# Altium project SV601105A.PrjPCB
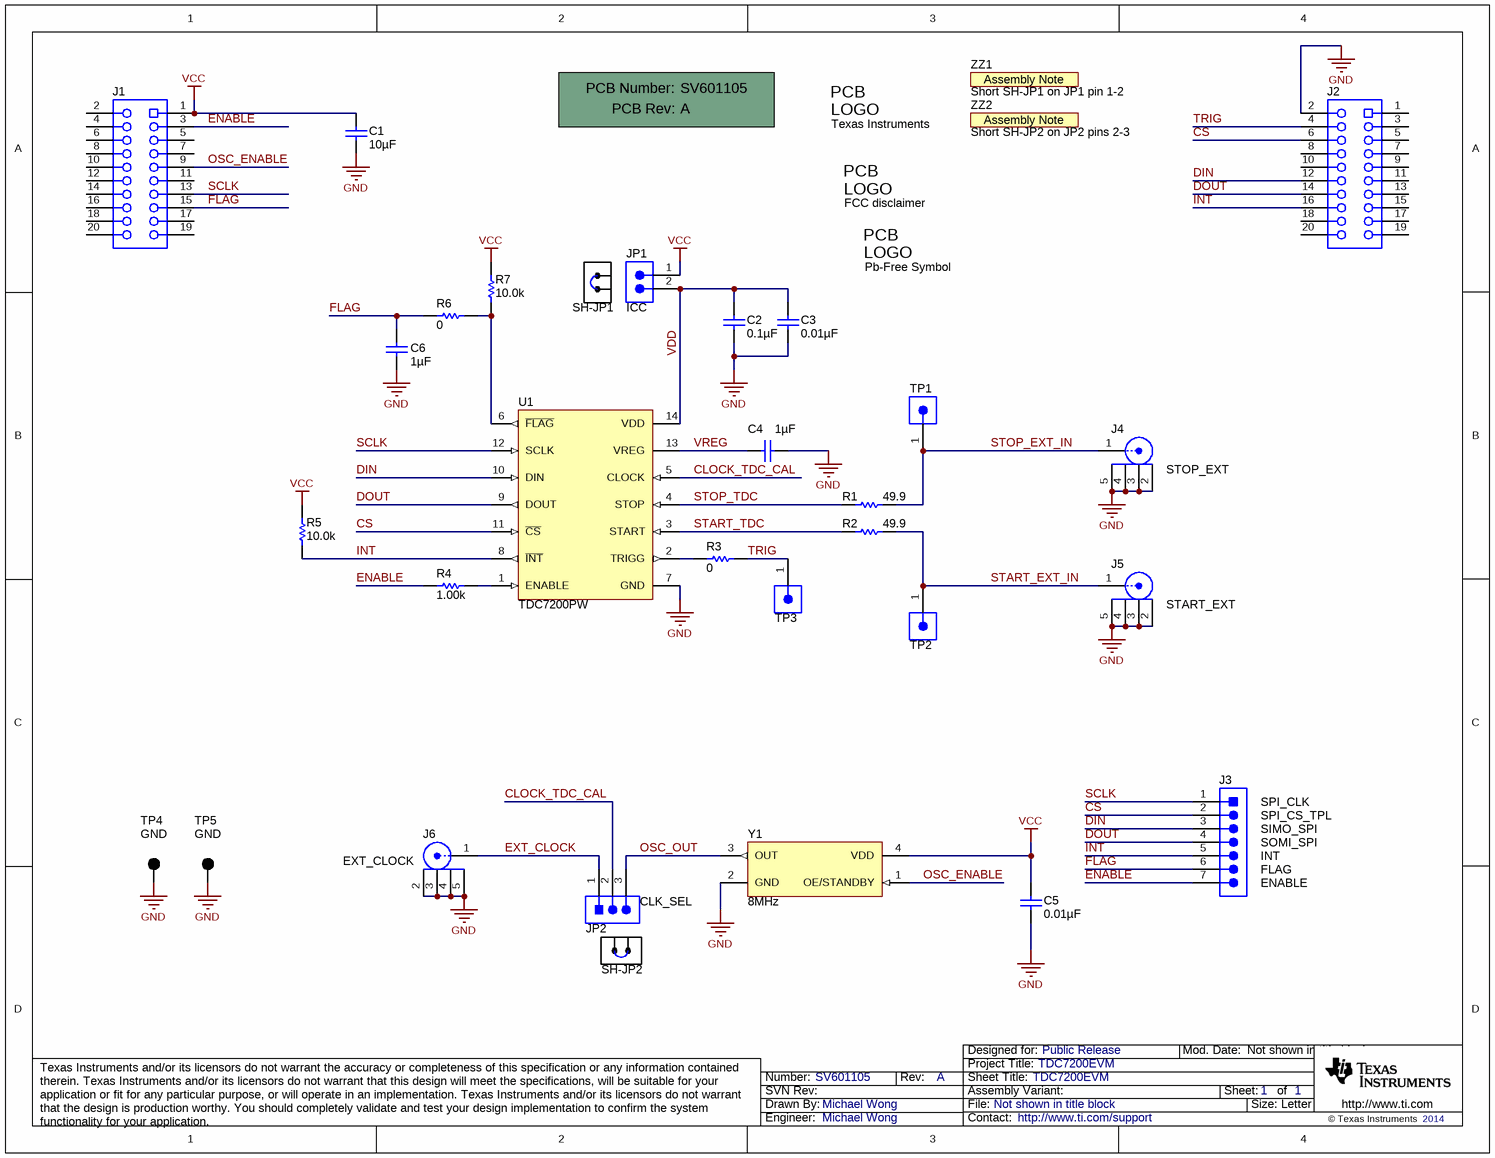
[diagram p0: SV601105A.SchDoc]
CopyrightYear: 2014; PCB_Layout: Michael Wong; PCB_Rev: A; PRJ_Customer: Public Release; PRJ_Engineer: Michael Wong; PRJ_Number: SV601105; PRJ_Title: TDC7200EVM; SCH_Rev: A; TechSupport: http://www.ti.com/support
1 sheet, 36 parts. Net scope: global (net labels, ports and power ports of the same name join across sheets).
Board file: SV601105A.PcbDoc

## Sheet SV601105A.SchDoc: TDC7200EVM
size Letter; Date: Not shown in title block; ApprovedBy: Not shown in title block; CheckedBy: Not shown in title block; Author: Not shown in title block; CompanyName: Not shown in title block; DrawnBy: Michael Wong; Engineer: Michael Wong; Organization: Not shown in title block; Address1: Not shown in title block; Address2: Not shown in title block; Address3: Not shown in title block; Address4: Not shown in title block; DocumentNumber: 1; Revision: Use project parameter SCH_Rev; SheetNumber: 1; SheetTotal: 1; PageSetup: Record=PageOptions|CenterHorizontal=True|CenterVertical=True|PrintScale=1.00|XCorrection=1.00|YCorrection=1.00|PrintKind=0|BorderSize=5000000|LeftOffset=0|BottomOffset=0|Orientation=2|PaperLength=1000|PaperWidth=1000|Scale=100|PaperSource=15|PrintQuality=600|MediaType=1|DitherType=10|PaperKind=Letter|PrintScaleMode=1

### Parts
!PCB  Printed Circuit Board  (value not drawn)  (mechanical)
C1  ValueDisplayed: 10µF  [0603]  (hidden comment: C0603C106M9PACTU)
C2  ValueDisplayed: 0.1µF  [0603]  (hidden comment: 0603YC104JAT2A)
C3  ValueDisplayed: 0.01µF  [0603]  (hidden comment: 06031C103JAT2A)
C4  ValueDisplayed: 1µF  [0603]  (hidden comment: EMK107B7105KA-T)
C5  ValueDisplayed: 0.01µF  [0603]  (hidden comment: 06031C103JAT2A)
C6  ValueDisplayed: 1µF  [0603]  (hidden comment: EMK107B7105KA-T)
J1  PPPC102LFBN-RC  [Sullins_PPPC102LFBN-RC]  (value not drawn)
J2  PPPC102LFBN-RC  [Sullins_PPPC102LFBN-RC]  (value not drawn)
J3  TSW-107-07-G-S  [TSW-107-07-G-S]  (value not drawn)
J4  STOP_EXT  [JOHNSON_142-0701-801]
J5  START_EXT  [JOHNSON_142-0701-801]
J6  EXT_CLOCK  [JOHNSON_142-0701-801]
JP1  ICC  [TSW-102-07-G-S]
JP2  CLK_SEL  [TSW-103-07-G-S]
Logo1  Texas Instruments  [TI_Stacked_Overlay_Small]  (no BOM)
Logo2  FCC disclaimer  [FCC_disclaimer_stacked]  (no BOM)
Logo3  Pb-Free Symbol  [Pb-Free_Overlay_Medium]  (no BOM)
R1  value 49.9  [0603]  (hidden comment: CRCW060349R9FKEA)
R2  value 49.9  [0603]  (hidden comment: CRCW060349R9FKEA)
R3  value 0  [0603]  (hidden comment: CRCW06030000Z0EA)
R4  value 1.00k  [0603]  (hidden comment: CRCW06031K00FKEA)
R5  value 10.0k  [0603]  (hidden comment: CRCW060310K0FKEA)
R6  value 0  [0603]  (hidden comment: CRCW06030000Z0EA)
R7  value 10.0k  [0603]  (hidden comment: CRCW060310K0FKEA)
SH-JP1  969102-0000-DA  [SNT-100-BK-G]  (value not drawn)  (mechanical)
SH-JP2  969102-0000-DA  [SNT-100-BK-G]  (value not drawn)  (mechanical)
TP1  TSW-101-07-G-S  [TSW-101-07-G-S]  (value not drawn)
TP2  TSW-101-07-G-S  [TSW-101-07-G-S]  (value not drawn)
TP3  TSW-101-07-G-S  [TSW-101-07-G-S]  (value not drawn)
TP4  GND  [Keystone5011]
TP5  GND  [Keystone5011]
U1  TDC7200PW  [PW0014A_N]
Y1  Frequency: 8MHz  [Abracon_ASFLMB]  (hidden comment: ASFLMB-8.000MHZ-LY-T)
ZZ1  Short SH-JP1 on JP1 pin 1-2  [AssemblyNote]  (no BOM)
ZZ2  Short SH-JP2 on JP2 pins 2-3  [AssemblyNote]  (no BOM)

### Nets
GND: C1.2 C2.2 C3.2 C4.1 C5.2 C6.2 J2.2 J4.2 J4.3 J4.4 J4.5 J5.2 J5.3 J5.4 J5.5 J6.2 J6.3 J6.4 J6.5 TP4.1 TP5.1 U1.7(GND) Y1.2(GND)
VCC: C1.1 C5.1 J1.1 JP1.1 R5.2 R7.2 Y1.4(VDD)
CLOCK_TDC_CAL: JP2.2 U1.5(CLOCK)
CS: J2.6 J3.2 U1.11(~{CS})
DIN: J2.12 J3.3 U1.10(DIN)
DOUT: J2.14 J3.4 U1.9(DOUT)
ENABLE: J1.3 J3.7 R4.1
EXT_CLOCK: J6.1 JP2.1
FLAG: C6.1 J1.15 J3.6 R6.1
INT: J2.16 J3.5 R5.1 U1.8(~{INT})
OSC_ENABLE: J1.9 Y1.1(OE/STANDBY)
OSC_OUT: JP2.3 Y1.3(OUT)
SCLK: J1.13 J3.1 U1.12(SCLK)
START_EXT_IN: J5.1 R2.2 TP2.1
START_TDC: R2.1 U1.3(START)
STOP_EXT_IN: J4.1 R1.2 TP1.1
STOP_TDC: R1.1 U1.4(STOP)
TRIG: J2.4 R3.2 TP3.1
VDD: C2.1 C3.1 JP1.2 U1.14(VDD)
VREG: C4.2 U1.13(VREG)
NetR3_1: R3.1 U1.2(TRIGG)
NetR4_2: R4.2 U1.1(ENABLE)
NetR6_2: R6.2 R7.1 U1.6(~{FLAG})

Not connected (* = marked no-connect by the designer): J1 2 4 5 6 7 8 10 11 12 14 16 17 18 19 20; J2 1 3 5 7 8 9 10 11 13 15 17 18 19 20

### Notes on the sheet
- (near J3) SPI_CLK
- (near J3) SPI_CS_TPL
- (near J3) SIMO_SPI
- (near J3) SOMI_SPI
- (near J3) ENABLE
- (near J3) INT
- (near J3) FLAG

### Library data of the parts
!PCB = PCB: Manufacturer: Any; PartNumber: SV601105; SymbolCreator: a0412235
C1 = C0603C106M9PACTU: CAP, CERM, 10uF, 6.3V, +/-20%, X5R, 0603; Manufacturer: Kemet; Polarized: N; CompType: Capacitor; U/M: EA; Cap_F: 0.00001; Tolerance_%: 20; ESR_Ohm: 0.004; Value1: 0.004 ohm; VDC_V: 6.3; IRMS_A: 8.9; TaMin_C: -55; TaMax_C: 85
C2 = 0603YC104JAT2A: CAP, CERM, 0.1uF, 16V, +/-5%, X7R, 0603; Manufacturer: AVX; Polarized: N; CompType: Capacitor; U/M: EA; Cap_F: 0.0000001; Tolerance_%: 5; ESR_Ohm: 0.039; Value1: 0.039 ohm; VDC_V: 16; TaMin_C: -55; TaMax_C: 125
C3 C5 = 06031C103JAT2A: CAP, CERM, 0.01uF, 100V, +/-5%, X7R, 0603; Manufacturer: AVX; Polarized: N; CompType: Capacitor; U/M: EA; Cap_F: 0.00000001; Tolerance_%: 5; ESR_Ohm: 0.098; Value1: 0.098 ohm; VDC_V: 100; TaMin_C: -55; TaMax_C: 125
C4 C6 = EMK107B7105KA-T: CAP, CERM, 1uF, 16V, +/-10%, X7R, 0603; Manufacturer: Taiyo Yuden; Polarized: N; CompType: Capacitor; U/M: EA; Cap_F: 0.000001; Tolerance_%: 10; Value1: Unknown; VDC_V: 16; TaMin_C: -55; TaMax_C: 85
J1 J2 = PPPC102LFBN-RC: Receptacle, 10x2, 100mil, TH; Manufacturer: Sullins Connector Solutions; SymbolCreator: a0412235; U/M: EA
J3 = TSW-107-07-G-S: Header, TH, 100mil, 7x1, Gold plated, 230 mil above insulator; Manufacturer: Samtec; SymbolCreator: a0411947; U/M: EA
J4-J6 = 142-0701-801: Connector, End launch SMA, 50 ohm, SMT; Manufacturer: Johnson; SymbolCreator: X0208326; U/M: EA
JP1 = TSW-102-07-G-S: Header, TH, 100mil, 2x1, Gold plated, 230 mil above insulator; Manufacturer: Samtec; SymbolCreator: a0412235; U/M: EA
JP2 = TSW-103-07-G-S: Header, TH, 100mil, 3x1, Gold plated, 230 mil above insulator; Manufacturer: Samtec; SymbolCreator: a0799628; U/M: EA
Logo1 = TI_Logo: Texas Instrument Corporate Signature; SymbolCreator: codlsc
Logo2 = FCC_disclaimer: SymbolCreator: codlsc
Logo3 = Pb-Free: SymbolCreator: a0412235
R1 R2 = CRCW060349R9FKEA: RES, 49.9 ohm, 1%, 0.1W, 0603; Manufacturer: Vishay-Dale; CompType: Resistor; Value_Code: 49R9; Tolerance_%: 1; Power_W: 0.1; VDC_V: 75; TempCo: 100 ppm/C; EIA_Code: E96; U/M: EA
R3 R6 = CRCW06030000Z0EA: RES, 0 ohm, 5%, 0.1W, 0603; Manufacturer: Vishay-Dale; CompType: Resistor; Value_Code: 0000; Tolerance_%: 5; Power_W: 0.1; VDC_V: 75; TempCo: 200 ppm/C; EIA_Code: E24; U/M: EA
R4 = CRCW06031K00FKEA: RES, 1.00k ohm, 1%, 0.1W, 0603; Manufacturer: Vishay-Dale; CompType: Resistor; Res_ohm: 1000; Value_Code: 1k00; Tolerance_%: 1; Power_W: 0.1; VDC_V: 75; TempCo: 100 ppm/C; EIA_Code: E96; U/M: EA
R5 R7 = CRCW060310K0FKEA: RES, 10.0k ohm, 1%, 0.1W, 0603; Manufacturer: Vishay-Dale; CompType: Resistor; Res_ohm: 10000; Value_Code: 10k0; Tolerance_%: 1; Power_W: 0.1; VDC_V: 75; TempCo: 100 ppm/C; EIA_Code: E96; U/M: EA
SH-JP1 SH-JP2 = 969102-0000-DA: Shunt, 100mil, Gold plated, Black; Manufacturer: 3M; Alternate Manufacturer: Samtec; Value: 1x2; Note: You can "mate" this to a header by matching the designator.  i.e. use SH-J3 for header J3
TP1-TP3 = TSW-101-07-G-S: Header, TH, 100mil, 1pos, Gold plated, 230 mil above insulator; Manufacturer: Samtec; SymbolCreator: a0412235; U/M: EA
TP4 TP5 = 5011: Test Point, Multipurpose, Black, TH; Manufacturer: Keystone; CompType: Test Point Loop; U/M: EA
U1 = TDC7200PW: STOPWATCH IC FOR TIME MEASUREMENT BETWEEN TWO EVENTS, PW0014A; Alternate Manufacturer: None; Manufacturer: Texas Instruments; SymbolCreator: a0411947; U/M: EA
Y1 = ASFLMB-8.000MHZ-LY-T: OSC, 8MHz, 15pF, SMD; Manufacturer: Abracon Corportation; SymbolCreator: x0208326; CompType: Oscillator; U/M: EA; TaMin_C: -40; TaMax_C: 85; Frequency Stability: ±10ppm
ZZ1 ZZ2 = AssemblyNote: SymbolCreator: codlsc

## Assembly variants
001: not fitted C3 C6 J3 R7 TP1 TP2 TP3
